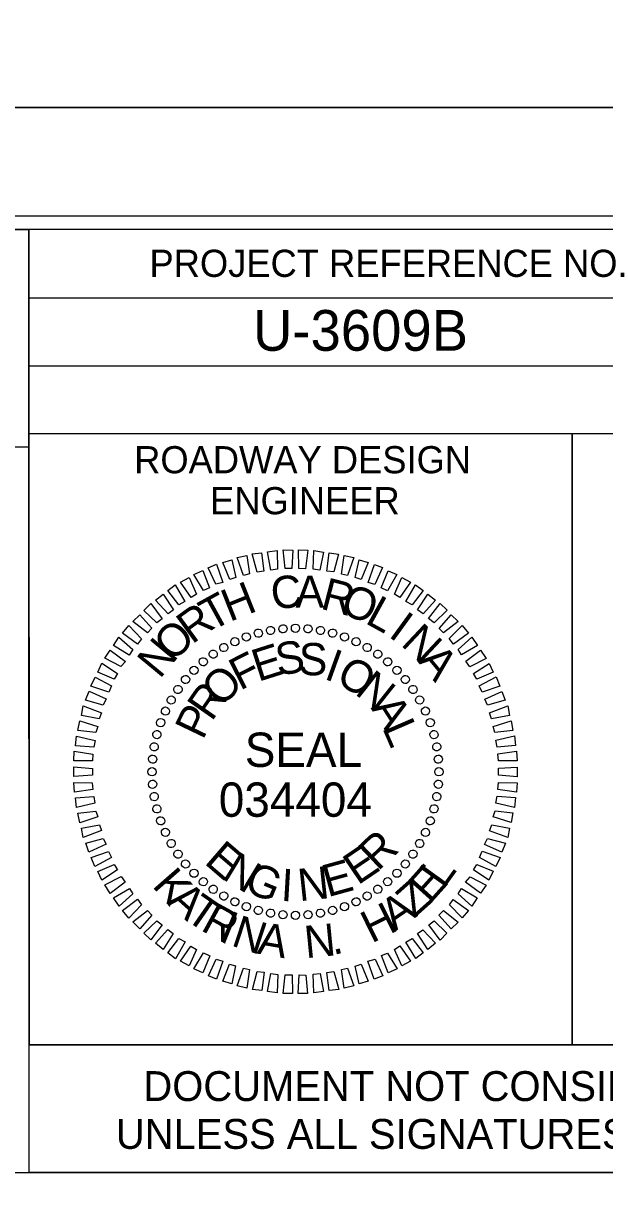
# Model space of a CAD drawing. Extents: x 2320980 to 2456309, y 595047 to 606177.
# Drawn here: x 2456001.89 to 2456023.3, y 595825.59 to 595868.66 of the extents above; entities that cross this region are included whole.
import ezdxf

# ---------------------------------------------------------------- set-up
doc = ezdxf.new("R2010")
doc.units = 0
for name, color, linetype in [('Prop Dimension', 7, 'Continuous'), ('Scratch_Level_0', 7, 'Continuous'), ('Sheet Data Field CELL', 7, 'Continuous'), ('Sheet Plan CELL', 7, 'Continuous'), ('Sheet Plot Border Inside CELL', 7, 'Continuous'), ('Sheet Plot Border Outside CELL', 7, 'Continuous'), ('Sheet Sticker Exception Certification CELL', 7, 'Continuous')]:
    doc.layers.add(name, color=color, linetype=linetype)

msp = doc.modelspace()

# ---------------------------------------------------------------- linework, layer by layer
at = {"layer": 'Prop Dimension'}
msp.add_lwpolyline([(2455998.637, 595826.366), (2456042.107, 595826.366), (2456042.107, 595822.09), (2455998.637, 595822.09)], close=True, dxfattribs=at)
at = {"layer": 'Scratch_Level_0'}
msp.add_lwpolyline([(2455979.323, 595861.076), (2456002.097, 595861.079), (2456002.098, 595853.07), (2455979.324, 595853.067)], close=True, dxfattribs=at)
at = {"layer": 'Sheet Data Field CELL'}
for p, q in [((2456011.001, 595846.316), (2456011.001, 595846.316)), ((2456011.453, 595846.387), (2456011.453, 595846.387)), ((2456011.916, 595846.406), (2456011.916, 595846.406)), ((2456012.38, 595846.383), (2456012.38, 595846.383)), ((2456012.834, 595846.317), (2456012.834, 595846.317)), ((2456009.681, 595845.914), (2456009.681, 595845.914)), ((2456010.099, 595846.09), (2456010.099, 595846.09)), ((2456010.539, 595846.224), (2456010.539, 595846.224)), ((2456013.278, 595846.23), (2456013.278, 595846.23)), ((2456013.722, 595846.09), (2456013.722, 595846.09)), ((2456014.147, 595845.908), (2456014.147, 595845.908)), ((2456009.274, 595845.696), (2456009.274, 595845.696)), ((2456014.561, 595845.704), (2456014.561, 595845.704)), ((2456014.945, 595845.448), (2456014.945, 595845.448)), ((2456008.514, 595845.177), (2456008.514, 595845.177)), ((2456008.878, 595845.447), (2456008.878, 595845.447)), ((2456015.319, 595845.17), (2456015.319, 595845.17)), ((2456008.172, 595844.855), (2456008.172, 595844.855)), ((2456015.65, 595844.86), (2456015.65, 595844.86)), ((2456007.862, 595844.523), (2456007.862, 595844.523)), ((2456015.972, 595844.518), (2456015.972, 595844.518)), ((2456007.327, 595843.766), (2456007.327, 595843.766)), ((2456007.584, 595844.15), (2456007.584, 595844.15)), ((2456016.242, 595844.154), (2456016.242, 595844.154)), ((2456016.491, 595843.758), (2456016.491, 595843.758)), ((2456007.124, 595843.352), (2456007.124, 595843.352)), ((2456016.709, 595843.351), (2456016.709, 595843.351)), ((2456006.941, 595842.927), (2456006.941, 595842.927)), ((2456016.885, 595842.932), (2456016.885, 595842.932)), ((2456006.802, 595842.483), (2456006.802, 595842.483)), ((2456017.019, 595842.492), (2456017.019, 595842.492)), ((2456006.715, 595842.039), (2456006.715, 595842.039)), ((2456017.111, 595842.031), (2456017.111, 595842.031)), ((2456006.649, 595841.585), (2456006.649, 595841.585)), ((2456017.183, 595841.579), (2456017.183, 595841.579)), ((2456006.625, 595841.121), (2456006.625, 595841.121)), ((2456017.201, 595841.116), (2456017.201, 595841.116)), ((2456006.644, 595840.658), (2456006.644, 595840.658)), ((2456017.178, 595840.652), (2456017.178, 595840.652)), ((2456006.715, 595840.206), (2456006.715, 595840.206)), ((2456017.112, 595840.198), (2456017.112, 595840.198)), ((2456006.807, 595839.744), (2456006.807, 595839.744)), ((2456017.025, 595839.754), (2456017.025, 595839.754)), ((2456006.942, 595839.304), (2456006.942, 595839.304)), ((2456016.885, 595839.309), (2456016.885, 595839.309)), ((2456007.117, 595838.886), (2456007.117, 595838.886)), ((2456016.703, 595838.884), (2456016.703, 595838.884)), ((2456007.335, 595838.479), (2456007.335, 595838.479)), ((2456016.499, 595838.47), (2456016.499, 595838.47)), ((2456007.584, 595838.083), (2456007.584, 595838.083)), ((2456007.854, 595837.719), (2456007.854, 595837.719)), ((2456015.965, 595837.713), (2456015.965, 595837.713)), ((2456016.243, 595838.086), (2456016.243, 595838.086)), ((2456008.176, 595837.377), (2456008.176, 595837.377)), ((2456015.655, 595837.381), (2456015.655, 595837.381)), ((2456008.508, 595837.067), (2456008.508, 595837.067)), ((2456015.313, 595837.059), (2456015.313, 595837.059)), ((2456008.881, 595836.789), (2456008.881, 595836.789)), ((2456009.265, 595836.532), (2456009.265, 595836.532)), ((2456014.553, 595836.54), (2456014.553, 595836.54)), ((2456014.949, 595836.789), (2456014.949, 595836.789)), ((2456009.679, 595836.329), (2456009.679, 595836.329)), ((2456010.104, 595836.146), (2456010.104, 595836.146)), ((2456010.549, 595836.007), (2456010.549, 595836.007)), ((2456013.287, 595836.012), (2456013.287, 595836.012)), ((2456013.728, 595836.146), (2456013.728, 595836.146)), ((2456014.146, 595836.322), (2456014.146, 595836.322)), ((2456010.993, 595835.92), (2456010.993, 595835.92)), ((2456011.447, 595835.854), (2456011.447, 595835.854)), ((2456011.911, 595835.83), (2456011.911, 595835.83)), ((2456012.374, 595835.849), (2456012.374, 595835.849)), ((2456012.826, 595835.92), (2456012.826, 595835.92))]:
    msp.add_line(p, q, dxfattribs=at)
for points in [[(2456009.493, 595848.197), (2456009.24, 595848.824), (2456009.565, 595848.924), (2456009.713, 595848.274)], [(2456009.996, 595848.342), (2456009.764, 595849.002), (2456010.12, 595849.082), (2456010.217, 595848.399)], [(2456010.5, 595848.467), (2456010.32, 595849.138), (2456010.667, 595849.176), (2456010.752, 595848.503)], [(2456011.004, 595848.539), (2456010.877, 595849.211), (2456011.234, 595849.259), (2456011.256, 595848.575)], [(2456011.53, 595848.601), (2456011.465, 595849.284), (2456011.813, 595849.28), (2456011.783, 595848.595)], [(2456012.035, 595848.599), (2456012.023, 595849.284), (2456012.371, 595849.279), (2456012.288, 595848.593)], [(2456012.563, 595848.577), (2456012.593, 595849.262), (2456012.941, 595849.205), (2456012.816, 595848.539)], [(2456013.07, 595848.501), (2456013.152, 595849.177), (2456013.501, 595849.13), (2456013.323, 595848.474)], [(2456013.609, 595848.395), (2456013.702, 595849.081), (2456014.061, 595849.003), (2456013.831, 595848.346)], [(2456014.116, 595848.267), (2456014.263, 595848.922), (2456014.591, 595848.823), (2456014.339, 595848.197)], [(2456008.521, 595847.79), (2456008.174, 595848.374), (2456008.497, 595848.527), (2456008.751, 595847.889)], [(2456008.98, 595848.019), (2456008.696, 595848.625), (2456009.01, 595848.757), (2456009.243, 595848.087)], [(2456014.593, 595848.085), (2456014.824, 595848.753), (2456015.121, 595848.632), (2456014.837, 595848.016)], [(2456015.071, 595847.894), (2456015.323, 595848.519), (2456015.652, 595848.378), (2456015.305, 595847.782)], [(2456008.073, 595847.529), (2456007.673, 595848.091), (2456007.996, 595848.265), (2456008.27, 595847.659)], [(2456015.559, 595847.66), (2456015.833, 595848.265), (2456016.152, 595848.092), (2456015.762, 595847.537)], [(2456007.219, 595846.935), (2456006.757, 595847.433), (2456007.038, 595847.659), (2456007.417, 595847.075)], [(2456007.614, 595847.258), (2456007.215, 595847.788), (2456007.485, 595847.993), (2456007.843, 595847.388)], [(2456015.975, 595847.383), (2456016.333, 595848), (2456016.611, 595847.784), (2456016.209, 595847.26)], [(2456016.412, 595847.074), (2456016.792, 595847.66), (2456017.07, 595847.433), (2456016.615, 595846.93)], [(2456006.804, 595846.601), (2456006.332, 595847.056), (2456006.581, 595847.314), (2456007.001, 595846.752)], [(2456016.818, 595846.755), (2456017.24, 595847.31), (2456017.498, 595847.062), (2456017.021, 595846.6)], [(2456006.463, 595846.226), (2456005.918, 595846.649), (2456006.177, 595846.896), (2456006.628, 595846.398)], [(2456017.204, 595846.393), (2456017.648, 595846.896), (2456017.905, 595846.647), (2456017.365, 595846.227)], [(2456006.101, 595845.82), (2456005.546, 595846.221), (2456005.773, 595846.499), (2456006.245, 595846.012)], [(2456017.579, 595846.02), (2456018.055, 595846.503), (2456018.281, 595846.222), (2456017.73, 595845.812)], [(2456005.792, 595845.414), (2456005.217, 595845.762), (2456005.412, 595846.071), (2456005.926, 595845.617)], [(2456017.902, 595845.615), (2456018.41, 595846.066), (2456018.616, 595845.764), (2456018.032, 595845.417)], [(2456005.484, 595844.988), (2456004.888, 595845.293), (2456005.094, 595845.592), (2456005.649, 595845.18)], [(2456018.183, 595845.188), (2456018.734, 595845.598), (2456018.94, 595845.286), (2456018.334, 595844.98)], [(2456005.239, 595844.53), (2456004.634, 595844.783), (2456004.786, 595845.112), (2456005.362, 595844.733)], [(2456018.465, 595844.73), (2456019.048, 595845.108), (2456019.191, 595844.784), (2456018.595, 595844.532)], [(2456005.037, 595844.042), (2456004.379, 595844.273), (2456004.532, 595844.602), (2456005.138, 595844.276)], [(2456018.684, 595844.281), (2456019.299, 595844.607), (2456019.442, 595844.273), (2456018.793, 595844.051)], [(2456004.834, 595843.575), (2456004.178, 595843.753), (2456004.309, 595844.082), (2456004.946, 595843.798)], [(2456018.882, 595843.789), (2456019.519, 595844.074), (2456019.641, 595843.749), (2456018.991, 595843.57)], [(2456004.685, 595843.067), (2456004.03, 595843.193), (2456004.097, 595843.541), (2456004.765, 595843.29)], [(2456019.059, 595843.286), (2456019.729, 595843.54), (2456019.798, 595843.194), (2456019.137, 595843.067)], [(2456004.557, 595842.559), (2456003.902, 595842.632), (2456003.97, 595842.991), (2456004.637, 595842.782)], [(2456019.194, 595842.783), (2456019.854, 595842.995), (2456019.924, 595842.638), (2456019.261, 595842.563)], [(2456019.298, 595842.279), (2456019.98, 595842.439), (2456020.018, 595842.081), (2456019.345, 595842.027)], [(2456004.482, 595842.021), (2456003.807, 595842.072), (2456003.843, 595842.431), (2456004.53, 595842.274)], [(2456004.438, 595841.514), (2456003.753, 595841.523), (2456003.768, 595841.871), (2456004.455, 595841.767)], [(2456019.37, 595841.775), (2456020.053, 595841.871), (2456020.08, 595841.514), (2456019.395, 595841.523)], [(2456004.437, 595840.988), (2456003.753, 595840.944), (2456003.747, 595841.302), (2456004.432, 595841.24)], [(2456019.39, 595841.249), (2456020.074, 595841.292), (2456020.08, 595840.934), (2456019.394, 595840.996)], [(2456004.456, 595840.461), (2456003.774, 595840.365), (2456003.746, 595840.723), (2456004.431, 595840.714)], [(2456019.388, 595840.722), (2456020.073, 595840.713), (2456020.058, 595840.365), (2456019.372, 595840.469)], [(2456004.529, 595839.957), (2456003.847, 595839.798), (2456003.809, 595840.155), (2456004.482, 595840.209)], [(2456019.344, 595840.216), (2456020.02, 595840.164), (2456019.984, 595839.805), (2456019.296, 595839.962)], [(2456004.632, 595839.453), (2456003.972, 595839.242), (2456003.903, 595839.598), (2456004.565, 595839.673)], [(2456019.27, 595839.677), (2456019.924, 595839.604), (2456019.856, 595839.245), (2456019.189, 595839.454)], [(2456004.767, 595838.95), (2456004.098, 595838.696), (2456004.028, 595839.042), (2456004.69, 595839.17)], [(2456019.142, 595839.169), (2456019.797, 595839.044), (2456019.729, 595838.695), (2456019.061, 595838.947)], [(2456004.945, 595838.447), (2456004.307, 595838.162), (2456004.186, 595838.487), (2456004.835, 595838.667)], [(2456018.992, 595838.661), (2456019.649, 595838.483), (2456019.517, 595838.154), (2456018.88, 595838.438)], [(2456005.143, 595837.956), (2456004.527, 595837.629), (2456004.384, 595837.964), (2456005.033, 595838.186)], [(2456018.79, 595838.194), (2456019.447, 595837.963), (2456019.295, 595837.634), (2456018.689, 595837.961)], [(2456005.361, 595837.507), (2456004.778, 595837.128), (2456004.635, 595837.452), (2456005.231, 595837.705)], [(2456018.588, 595837.706), (2456019.193, 595837.453), (2456019.04, 595837.124), (2456018.465, 595837.504)], [(2456005.643, 595837.048), (2456005.092, 595836.638), (2456004.886, 595836.951), (2456005.492, 595837.256)], [(2456018.343, 595837.249), (2456018.938, 595836.943), (2456018.733, 595836.645), (2456018.178, 595837.056)], [(2456005.924, 595836.621), (2456005.416, 595836.17), (2456005.211, 595836.472), (2456005.795, 595836.819)], [(2456006.248, 595836.216), (2456005.771, 595835.734), (2456005.545, 595836.014), (2456006.096, 595836.424)], [(2456017.725, 595836.416), (2456018.28, 595836.015), (2456018.053, 595835.737), (2456017.581, 595836.224)], [(2456018.034, 595836.822), (2456018.609, 595836.474), (2456018.415, 595836.165), (2456017.901, 595836.62)], [(2456006.623, 595835.843), (2456006.179, 595835.341), (2456005.921, 595835.589), (2456006.462, 595836.009)], [(2456017.364, 595836.01), (2456017.909, 595835.587), (2456017.649, 595835.341), (2456017.198, 595835.838)], [(2456007.008, 595835.481), (2456006.586, 595834.926), (2456006.329, 595835.175), (2456006.805, 595835.636)], [(2456017.023, 595835.635), (2456017.494, 595835.18), (2456017.246, 595834.923), (2456016.825, 595835.484)], [(2456007.414, 595835.162), (2456007.035, 595834.576), (2456006.757, 595834.803), (2456007.212, 595835.306)], [(2456016.607, 595835.301), (2456017.069, 595834.804), (2456016.788, 595834.578), (2456016.41, 595835.161)], [(2456007.851, 595834.854), (2456007.493, 595834.236), (2456007.216, 595834.453), (2456007.617, 595834.976)], [(2456008.267, 595834.577), (2456007.993, 595833.971), (2456007.674, 595834.145), (2456008.065, 595834.699)], [(2456015.754, 595834.707), (2456016.154, 595834.145), (2456015.83, 595833.971), (2456015.556, 595834.577)], [(2456016.213, 595834.979), (2456016.612, 595834.448), (2456016.341, 595834.243), (2456015.983, 595834.848)], [(2456008.756, 595834.343), (2456008.503, 595833.717), (2456008.174, 595833.859), (2456008.522, 595834.455)], [(2456015.306, 595834.446), (2456015.653, 595833.863), (2456015.329, 595833.71), (2456015.076, 595834.348)], [(2456009.233, 595834.151), (2456009.002, 595833.483), (2456008.705, 595833.604), (2456008.989, 595834.22)], [(2456009.71, 595833.97), (2456009.564, 595833.314), (2456009.235, 595833.414), (2456009.488, 595834.039)], [(2456010.218, 595833.842), (2456010.125, 595833.155), (2456009.765, 595833.233), (2456009.996, 595833.89)], [(2456013.83, 595833.894), (2456014.063, 595833.235), (2456013.706, 595833.155), (2456013.61, 595833.838)], [(2456014.333, 595834.04), (2456014.586, 595833.412), (2456014.262, 595833.312), (2456014.113, 595833.962)], [(2456014.846, 595834.217), (2456015.131, 595833.611), (2456014.817, 595833.479), (2456014.584, 595834.149)], [(2456010.757, 595833.735), (2456010.674, 595833.06), (2456010.326, 595833.106), (2456010.504, 595833.762)], [(2456011.264, 595833.66), (2456011.234, 595832.975), (2456010.885, 595833.032), (2456011.01, 595833.697)], [(2456011.791, 595833.637), (2456011.803, 595832.953), (2456011.455, 595832.957), (2456011.538, 595833.643)], [(2456012.297, 595833.636), (2456012.361, 595832.952), (2456012.014, 595832.957), (2456012.044, 595833.642)], [(2456012.822, 595833.697), (2456012.95, 595833.026), (2456012.593, 595832.977), (2456012.57, 595833.661)], [(2456013.327, 595833.769), (2456013.507, 595833.098), (2456013.16, 595833.061), (2456013.074, 595833.733)]]:
    msp.add_lwpolyline(points, close=True, dxfattribs=at)
for centre, major_axis in [((2456010.546, 595846.221), (-0.039, 0.146)), ((2456010.996, 595846.321), (-0.026, 0.149)), ((2456011.453, 595846.381), (-0.013, 0.151)), ((2456011.913, 595846.401), (0, 0.152)), ((2456012.374, 595846.381), (0.013, 0.151)), ((2456012.831, 595846.321), (0.026, 0.149)), ((2456013.281, 595846.221), (0.039, 0.146)), ((2456009.681, 595845.906), (-0.064, 0.137)), ((2456010.106, 595846.082), (-0.052, 0.143)), ((2456013.72, 595846.082), (0.052, 0.143)), ((2456014.146, 595845.906), (0.064, 0.137)), ((2456008.883, 595845.446), (-0.087, 0.124)), ((2456009.272, 595845.693), (-0.076, 0.131)), ((2456014.555, 595845.693), (0.076, 0.131)), ((2456014.943, 595845.446), (0.087, 0.124)), ((2456008.178, 595844.854), (-0.107, 0.107)), ((2456008.518, 595845.165), (-0.097, 0.116)), ((2456015.309, 595845.165), (0.097, 0.116)), ((2456015.649, 595844.854), (0.107, 0.107)), ((2456007.866, 595844.514), (-0.116, 0.097)), ((2456015.96, 595844.514), (0.116, 0.097)), ((2456007.586, 595844.148), (-0.124, 0.087)), ((2456016.241, 595844.148), (0.124, 0.087)), ((2456007.338, 595843.76), (-0.131, 0.076)), ((2456016.488, 595843.76), (0.131, 0.076)), ((2456007.125, 595843.351), (-0.137, 0.064)), ((2456016.701, 595843.351), (0.137, 0.064)), ((2456006.949, 595842.925), (-0.143, 0.052)), ((2456016.877, 595842.925), (0.143, 0.052)), ((2456006.81, 595842.485), (-0.146, 0.039)), ((2456017.016, 595842.485), (0.146, 0.039)), ((2456006.711, 595842.035), (-0.149, 0.026)), ((2456017.116, 595842.035), (0.149, 0.026)), ((2456006.651, 595841.579), (-0.151, 0.013)), ((2456017.176, 595841.579), (0.151, 0.013)), ((2456006.63, 595841.118), (-0.152, 0)), ((2456017.196, 595841.118), (0.152, 0)), ((2456006.651, 595840.658), (-0.151, -0.013)), ((2456017.176, 595840.658), (0.151, -0.013)), ((2456006.711, 595840.201), (-0.149, -0.026)), ((2456017.116, 595840.201), (0.149, -0.026)), ((2456006.81, 595839.751), (-0.146, -0.039)), ((2456017.016, 595839.751), (0.146, -0.039)), ((2456006.949, 595839.311), (-0.143, -0.052)), ((2456016.877, 595839.311), (0.143, -0.052)), ((2456007.125, 595838.886), (-0.137, -0.064)), ((2456016.701, 595838.886), (0.137, -0.064)), ((2456007.338, 595838.477), (-0.131, -0.076)), ((2456016.488, 595838.477), (0.131, -0.076)), ((2456007.586, 595838.088), (-0.124, -0.087)), ((2456016.241, 595838.088), (0.124, -0.087)), ((2456007.866, 595837.722), (-0.116, -0.097)), ((2456015.96, 595837.722), (0.116, -0.097)), ((2456008.178, 595837.383), (-0.107, -0.107)), ((2456015.649, 595837.383), (0.107, -0.107)), ((2456008.518, 595837.071), (-0.097, -0.116)), ((2456008.883, 595836.791), (-0.087, -0.124)), ((2456014.943, 595836.791), (0.087, -0.124)), ((2456015.309, 595837.071), (0.097, -0.116)), ((2456009.272, 595836.543), (-0.076, -0.131)), ((2456009.681, 595836.33), (-0.064, -0.137)), ((2456014.146, 595836.33), (0.064, -0.137)), ((2456014.555, 595836.543), (0.076, -0.131)), ((2456010.106, 595836.154), (-0.052, -0.143)), ((2456010.546, 595836.015), (-0.039, -0.146)), ((2456010.996, 595835.916), (-0.026, -0.149)), ((2456011.453, 595835.855), (-0.013, -0.151)), ((2456011.913, 595835.835), (0, -0.152)), ((2456012.374, 595835.855), (0.013, -0.151)), ((2456012.831, 595835.916), (0.026, -0.149)), ((2456013.281, 595836.015), (0.039, -0.146)), ((2456013.72, 595836.154), (0.052, -0.143))]:
    msp.add_ellipse(centre, major_axis=major_axis, ratio=0.999708, dxfattribs=at)
at = {"layer": 'Sheet Plan CELL'}
for p, q in [((2456002.097, 595853.564), (2456002.097, 595861.079)), ((2456002.094, 595858.569), (2456042.104, 595858.566)), ((2456002.097, 595856.061), (2456042.104, 595856.066))]:
    msp.add_line(p, q, dxfattribs=at)
for points in [[(2455742.104, 595651.076), (2455742.099, 595861.071), (2456002.097, 595861.079), (2456002.099, 595831.066), (2456042.107, 595831.064), (2456042.107, 595651.076)], [(2456042.112, 595861.076), (2455742.104, 595861.076), (2455742.104, 595651.076), (2456042.107, 595651.076)], [(2456002.097, 595853.564), (2456022.107, 595853.564), (2456022.107, 595831.061), (2456002.099, 595831.066)], [(2456022.107, 595853.564), (2456042.104, 595853.566), (2456042.107, 595831.064), (2456022.107, 595831.061)]]:
    msp.add_lwpolyline(points, close=True, dxfattribs=at)
at = {"layer": 'Sheet Plot Border Inside CELL'}
msp.add_lwpolyline([(2455711.407, 595650.574), (2456044.604, 595650.576), (2456044.607, 595861.574), (2455711.407, 595861.574)], close=True, dxfattribs=at)
at = {"layer": 'Sheet Plot Border Outside CELL'}
for points in [[(2455708.807, 595865.574), (2456045.507, 595865.574), (2456045.507, 596084.574), (2455708.807, 596084.574)], [(2455708.807, 595646.574), (2456045.507, 595646.574), (2456045.507, 595865.574), (2455708.807, 595865.574)]]:
    msp.add_lwpolyline(points, close=True, dxfattribs=at)
at = {"layer": 'Sheet Sticker Exception Certification CELL'}
for p, q in [((2456002.099, 595826.366), (2456002.099, 595831.066)), ((2456002.099, 595831.066), (2456042.107, 595831.066)), ((2456042.107, 595826.366), (2456002.099, 595826.366))]:
    msp.add_line(p, q, dxfattribs=at)

# ---------------------------------------------------------------- texts
at = {"layer": 'Sheet Data Field CELL'}
for s, height, rotation, p in [('U-3609B', 1.5, 0, (2456010.352, 595856.614)), ('H', 1.188, 21.6195, (2456009.489, 595846.627)), ('C', 1.188, 7.2199, (2456011.082, 595847.076)), ('A', 1.187, 0.0203, (2456011.913, 595847.154)), ('R', 1.188, 345.6211, (2456012.798, 595847.127)), ('T', 1.188, 28.8198, (2456008.811, 595846.267)), ('O', 1.187, 338.4212, (2456013.507, 595846.981)), ('R', 1.188, 36.0205, (2456008.103, 595845.792)), ('L', 1.188, 331.2209, (2456014.44, 595846.608)), ('I', 1.188, 324.0201, (2456015.302, 595846.117)), ('O', 1.188, 43.2217, (2456007.388, 595845.126)), ('N', 1.188, 316.8189, (2456015.761, 595845.799)), ('N', 1.188, 50.4235, (2456006.914, 595844.507)), ('S', 1.188, 8.2556, (2456011.262, 595844.657)), ('S', 1.188, 358.9004, (2456012.02, 595844.68)), ('F', 1.187, 26.967, (2456009.871, 595844.095)), ('E', 1.188, 17.6111, (2456010.539, 595844.423)), ('I', 1.188, 340.1896, (2456012.928, 595844.549)), ('A', 1.188, 309.6172, (2456016.393, 595845.188)), ('O', 1.187, 330.8335, (2456013.352, 595844.409)), ('O', 1.188, 45.6812, (2456009.186, 595843.462)), ('N', 1.188, 321.4766, (2456014.064, 595844)), ('R', 1.188, 55.0397, (2456008.827, 595842.939)), ('A', 1.188, 302.7603, (2456014.674, 595843.463)), ('P', 1.188, 64.3989, (2456008.502, 595842.259)), ('L', 1.188, 293.4009, (2456015.098, 595842.743)), ('SEAL', 1.2634, 0, (2456010.046, 595841.296)), ('034404', 1.2638, 0, (2456009.089, 595839.46)), ('E', 1.188, 319.2769, (2456008.517, 595837.762)), ('R', 1.188, 43.4814, (2456014.948, 595837.432)), ('N', 1.188, 328.634, (2456009.159, 595837.204)), ('E', 1.188, 34.1241, (2456014.209, 595836.924)), ('G', 1.188, 337.9902, (2456009.967, 595836.744)), ('E', 1.188, 15.4118, (2456013.1, 595836.494)), ('E', 1.188, 48.1243, (2456016.869, 595836.232)), ('L', 1.188, 54.2991, (2456017.366, 595836.78)), ('K', 1.188, 311.168, (2456006.605, 595836.914)), ('I', 1.188, 356.7012, (2456011.354, 595836.368)), ('N', 1.188, 6.0564, (2456012.06, 595836.349)), ('A', 1.188, 318.0722, (2456007.149, 595836.292)), ('Z', 1.188, 41.5848, (2456016.281, 595835.714)), ('T', 1.188, 325.3219, (2456007.797, 595835.713)), ('A', 1.188, 34.3351, (2456015.565, 595835.222)), ('R', 1.188, 331.3047, (2456008.384, 595835.301)), ('I', 1.188, 337.7098, (2456009.055, 595834.929)), ('H', 1.188, 26.3751, (2456014.715, 595834.79)), ('N', 1.188, 341.8307, (2456009.508, 595834.731)), ('A', 1.188, 350.2514, (2456010.47, 595834.429)), ('N', 1.188, 5.5954, (2456012.296, 595834.252)), ('.', 1.188, 14.016, (2456013.299, 595834.364))]:
    msp.add_text(s, height=height, rotation=rotation, dxfattribs=at).set_placement(p)
at = {"layer": 'Sheet Plan CELL'}
for s, height, p in [('PROJECT REFERENCE NO.', 1.00002, (2456006.537, 595859.334)), ('ROADWAY DESIGN', 1.00002, (2456005.972, 595852.104)), ('ENGINEER', 1, (2456008.769, 595850.596))]:
    msp.add_text(s, height=height, rotation=0, dxfattribs=at).set_placement(p)
at = {"layer": 'Sheet Sticker Exception Certification CELL'}
for s, p in [('DOCUMENT NOT CONSIDERED FINAL', (2456006.313, 595828.997)), ('UNLESS ALL SIGNATURES COMPLETED', (2456005.299, 595827.237))]:
    msp.add_text(s, height=1.1, dxfattribs=at).set_placement(p)

doc.saveas('drawing.dxf')
